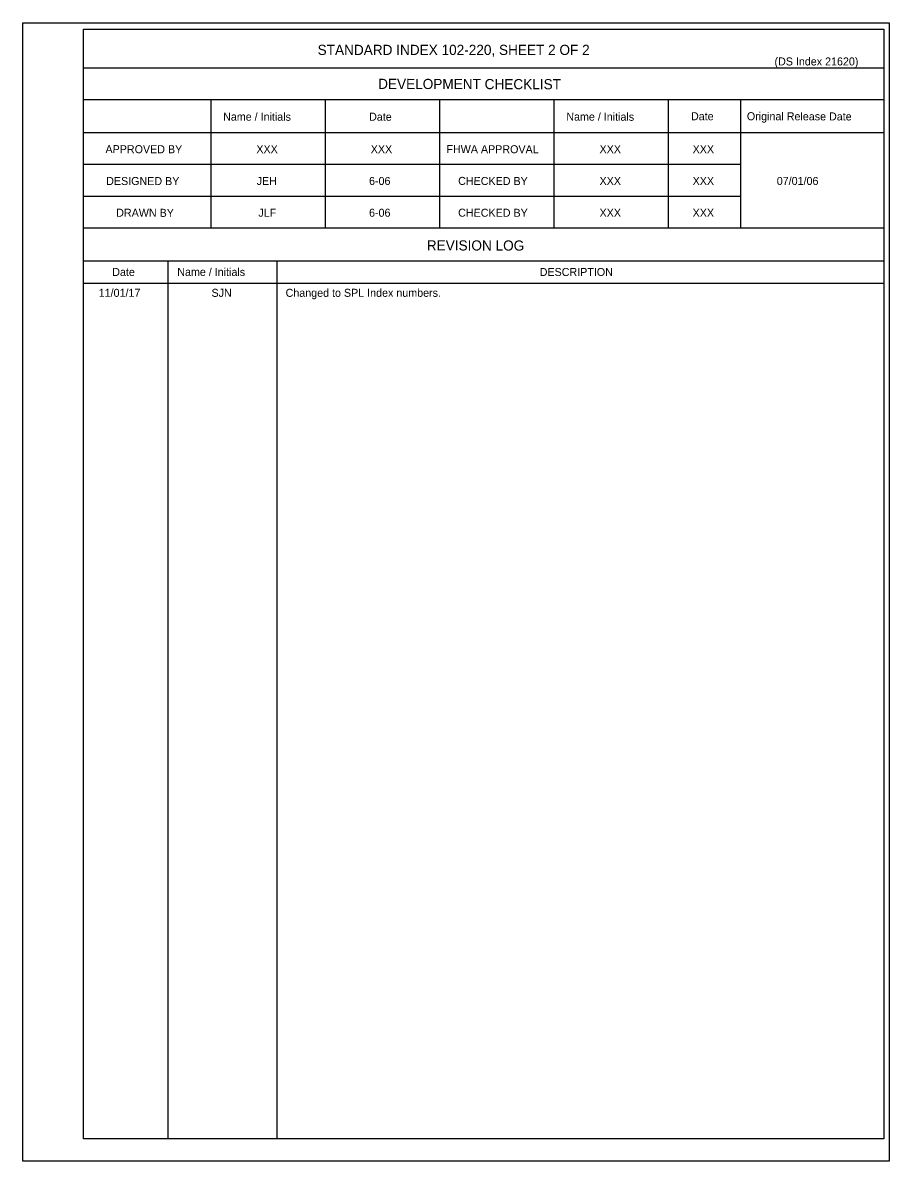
# Model space of a CAD drawing. Extents: x 10624 to 10731, y 76457 to 76509.
# Drawn here: x 10698.18 to 10730.9, y 76465.91 to 76508.91 of the extents above; entities that cross this region are included whole.
import ezdxf

# ---------------------------------------------------------------- set-up
doc = ezdxf.new("R2010")
doc.units = 0
for name, color, linetype in [('Border', 7, 'Continuous'), ('PlotBorder_dp', 7, 'Continuous'), ('TextStructures', 7, 'Continuous')]:
    doc.layers.add(name, color=color, linetype=linetype)

msp = doc.modelspace()

# ---------------------------------------------------------------- linework, layer by layer
at = {"layer": 'Border'}
for p, q in [((10730.698, 76507.194), (10700.478, 76507.194)), ((10730.698, 76505.994), (10700.478, 76505.994)), ((10705.278, 76505.994), (10705.278, 76501.153)), ((10709.598, 76505.994), (10709.598, 76501.153)), ((10713.918, 76505.994), (10713.918, 76501.153)), ((10718.238, 76505.994), (10718.238, 76501.153)), ((10722.558, 76505.994), (10722.558, 76501.153)), ((10725.28, 76505.994), (10725.28, 76501.153)), ((10730.698, 76504.753), (10700.478, 76504.753)), ((10725.28, 76503.553), (10700.478, 76503.553)), ((10725.28, 76502.353), (10700.478, 76502.353)), ((10730.698, 76501.153), (10700.478, 76501.153)), ((10730.698, 76499.911), (10700.478, 76499.911)), ((10703.658, 76499.911), (10703.658, 76466.751)), ((10707.772, 76499.911), (10707.772, 76466.751)), ((10730.698, 76499.065), (10700.478, 76499.065))]:
    msp.add_line(p, q, dxfattribs=at)
msp.add_lwpolyline([(10700.478, 76508.665), (10730.698, 76508.665), (10730.698, 76466.751), (10700.478, 76466.751)], close=True, dxfattribs=at)
at = {"layer": 'PlotBorder_dp'}
msp.add_line((10698.182, 76465.909), (10698.182, 76465.909), dxfattribs=at)
msp.add_lwpolyline([(10698.182, 76508.909), (10730.902, 76508.909), (10730.902, 76465.909), (10698.182, 76465.909)], close=True, dxfattribs=at)

# ---------------------------------------------------------------- texts
at = {"layer": 'TextStructures'}
for s, height, p in [('STANDARD INDEX 102-220, SHEET 2 OF 2', 0.384, (10709.317, 76507.693)), ('(DS Index 21620)', 0.3024, (10726.569, 76507.297)), ('XXX', 0.3024, (10707.003, 76503.983)), ('XXX', 0.3024, (10711.323, 76503.983)), ('XXX', 0.3024, (10719.963, 76503.983)), ('XXX', 0.3024, (10723.478, 76503.983)), ('JEH', 0.3024, (10707.014, 76502.783)), ('6-06', 0.3024, (10711.258, 76502.783)), ('XXX', 0.3024, (10719.963, 76502.783)), ('XXX', 0.3024, (10723.478, 76502.783)), ('07/01/06', 0.3024, (10726.655, 76502.783)), ('JLF', 0.3024, (10707.077, 76501.583)), ('6-06', 0.3024, (10711.258, 76501.583)), ('XXX', 0.3024, (10719.963, 76501.583)), ('XXX', 0.3024, (10723.478, 76501.583)), ('DESCRIPTION', 0.3024, (10717.703, 76499.345)), ('11/01/17', 0.3024, (10701.049, 76498.558)), ('SJN', 0.3024, (10705.31, 76498.558)), ('Changed to SPL Index numbers.', 0.3024, (10708.107, 76498.558))]:
    msp.add_text(s, height=height, dxfattribs=at).set_placement(p)
for s, height, p in [('DEVELOPMENT CHECKLIST', 0.384, (10711.601, 76506.41)), ('Name / Initials', 0.3024, (10705.747, 76505.213)), ('Date', 0.3024, (10711.259, 76505.21)), ('Name / Initials', 0.3024, (10718.707, 76505.213)), ('Date', 0.3024, (10723.416, 76505.228)), ('Original Release Date', 0.3024, (10725.526, 76505.228)), ('APPROVED BY', 0.3024, (10701.305, 76503.985)), ('FHWA APPROVAL', 0.3024, (10714.18, 76503.986)), ('DESIGNED BY', 0.3024, (10701.331, 76502.783)), ('CHECKED BY', 0.3024, (10714.623, 76502.785)), ('DRAWN BY', 0.3024, (10701.71, 76501.583)), ('CHECKED BY', 0.3024, (10714.623, 76501.585)), ('REVISION LOG', 0.384, (10713.439, 76500.311)), ('Date', 0.3024, (10701.561, 76499.346)), ('Name / Initials', 0.3024, (10704.016, 76499.349))]:
    msp.add_text(s, height=height, rotation=359.8756, dxfattribs=at).set_placement(p)

doc.saveas('drawing.dxf')
